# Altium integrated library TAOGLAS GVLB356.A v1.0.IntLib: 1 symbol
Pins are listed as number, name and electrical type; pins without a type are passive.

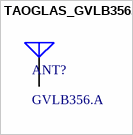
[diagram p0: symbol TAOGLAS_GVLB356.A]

## TAOGLAS_GVLB356.A
designator ANT?, comment GVLB356.A
GPS/GLONASS/BeiDou Single Feed Stacked Patch L1:1575MHz L5:1176.45MHz B1:1561MHz G1:1602MHz; ComponentLibStatus: Created; MFG: Taoglas; Temp_High: +85C; Temp_Low: -40C
footprint TAOGLAS_GVLB356.A (GPS/GLONASS/BeiDou Single Feed Stacked Patch L1:1575MHz L5:1176.45MHz B1:1561MHz G1:1602MHz)
pins: 1 RF FEED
